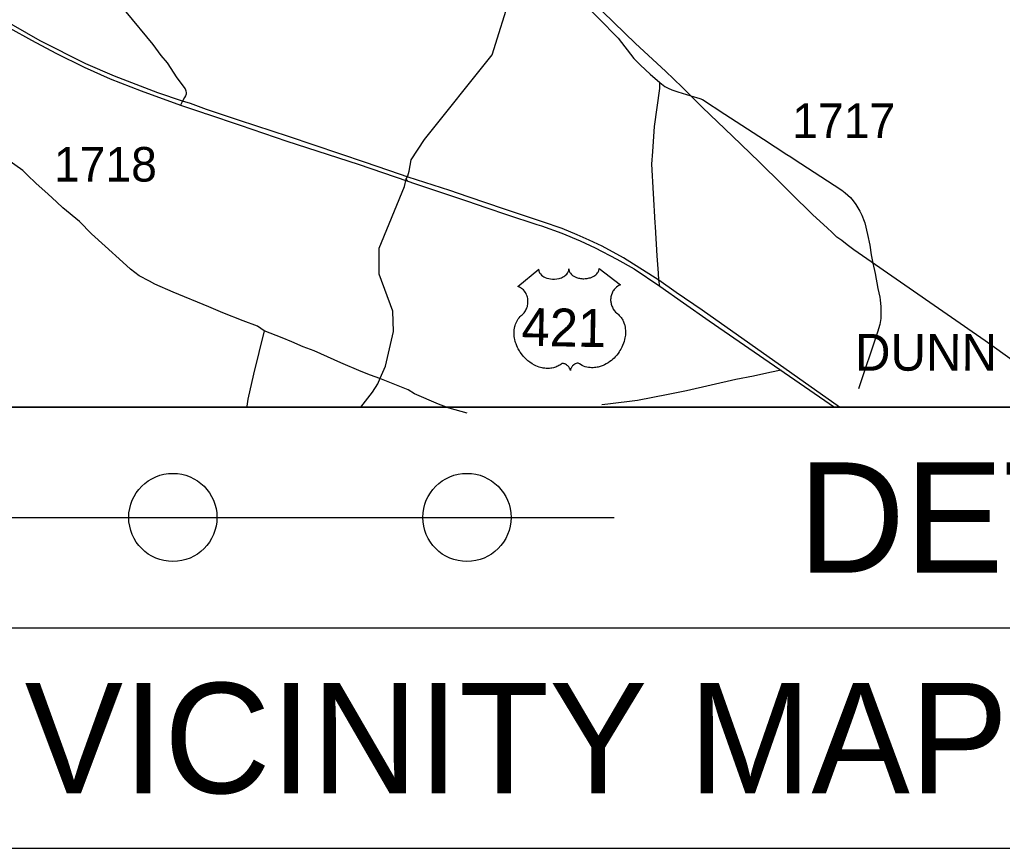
# Model space of a CAD drawing. Extents: x 0 to 2021, y 0 to 1321.
# Drawn here: x 408.2 to 541.9, y 888.1 to 1000.8 of the extents above; entities that cross this region are included whole.
import ezdxf

# ---------------------------------------------------------------- set-up
doc = ezdxf.new("R2010")
doc.units = 0
for name, color, linetype in [('Default', 7, 'Continuous'), ('Exist Hydro Stream or Body of Water', 7, 'Continuous'), ('Miscellaneous Lines', 7, 'Continuous'), ('Old_Level_26', 7, 'Continuous'), ('Scratch_Level_0', 7, 'Continuous'), ('Sheet Data Field CELL', 7, 'Continuous'), ('Sheet Title CELL', 7, 'Continuous'), ('Text', 7, 'Continuous')]:
    doc.layers.add(name, color=color, linetype=linetype)

msp = doc.modelspace()

# ---------------------------------------------------------------- linework, layer by layer
at = {"layer": 'Default'}
for p, q in [((475.98, 964.51), (478.81, 966.84)), ((478.82, 966.72), (478.81, 966.84)), ((478.82, 966.72), (478.85, 966.58)), ((482.83, 966.5), (482.89, 966.67)), ((482.89, 966.67), (482.91, 966.75)), ((482.91, 966.75), (482.92, 966.9)), ((482.92, 966.9), (482.93, 966.77)), ((482.93, 966.77), (482.94, 966.69)), ((482.94, 966.69), (482.97, 966.61)), ((482.97, 966.61), (483, 966.52)), ((486.93, 966.56), (486.98, 966.67)), ((486.98, 966.67), (487, 966.78)), ((487, 966.78), (487.02, 966.88)), ((487.02, 966.97), (489.92, 964.73)), ((487.02, 966.88), (487.02, 966.97)), ((478.85, 966.58), (478.88, 966.51)), ((478.88, 966.51), (478.94, 966.37)), ((478.94, 966.37), (479.06, 966.21)), ((479.06, 966.21), (479.21, 966.05)), ((479.21, 966.05), (479.38, 965.91)), ((479.38, 965.91), (479.5, 965.84)), ((479.5, 965.84), (479.7, 965.73)), ((479.7, 965.73), (479.92, 965.64)), ((479.92, 965.64), (480.17, 965.58)), ((480.17, 965.58), (480.42, 965.53)), ((480.42, 965.53), (480.7, 965.5)), ((480.7, 965.5), (480.97, 965.5)), ((480.97, 965.5), (481.26, 965.53)), ((481.26, 965.53), (481.59, 965.6)), ((481.59, 965.6), (481.74, 965.64)), ((481.74, 965.64), (481.9, 965.7)), ((481.9, 965.7), (482.06, 965.76)), ((482.06, 965.76), (482.23, 965.86)), ((482.23, 965.86), (482.36, 965.95)), ((482.36, 965.95), (482.47, 966.03)), ((482.47, 966.03), (482.62, 966.18)), ((482.62, 966.18), (482.74, 966.33)), ((482.74, 966.33), (482.79, 966.41)), ((482.79, 966.41), (482.83, 966.5)), ((483, 966.52), (483.06, 966.4)), ((483.06, 966.4), (483.13, 966.3)), ((483.13, 966.3), (483.26, 966.15)), ((483.26, 966.15), (483.34, 966.08)), ((483.34, 966.08), (483.42, 966.02)), ((483.42, 966.02), (483.61, 965.89)), ((483.61, 965.89), (483.84, 965.78)), ((483.84, 965.78), (483.96, 965.73)), ((483.96, 965.73), (484.07, 965.69)), ((484.07, 965.69), (484.22, 965.65)), ((484.22, 965.65), (484.37, 965.62)), ((484.37, 965.62), (484.52, 965.59)), ((484.52, 965.59), (484.67, 965.57)), ((484.67, 965.57), (484.83, 965.56)), ((484.83, 965.56), (484.95, 965.56)), ((484.95, 965.56), (485.11, 965.57)), ((485.11, 965.57), (485.25, 965.58)), ((485.25, 965.58), (485.4, 965.59)), ((485.4, 965.59), (485.56, 965.62)), ((485.56, 965.62), (485.69, 965.66)), ((485.69, 965.66), (485.86, 965.7)), ((485.86, 965.7), (486.02, 965.76)), ((486.02, 965.76), (486.15, 965.82)), ((486.15, 965.82), (486.33, 965.92)), ((486.33, 965.92), (486.47, 966.01)), ((486.47, 966.01), (486.58, 966.1)), ((486.58, 966.1), (486.7, 966.21)), ((486.7, 966.21), (486.82, 966.35)), ((486.82, 966.35), (486.89, 966.45)), ((486.89, 966.45), (486.93, 966.56)), ((476.07, 964.48), (475.98, 964.51)), ((476.21, 964.41), (476.07, 964.48)), ((476.36, 964.33), (476.21, 964.41)), ((476.48, 964.24), (476.36, 964.33)), ((476.6, 964.15), (476.48, 964.24)), ((476.73, 964.03), (476.6, 964.15)), ((476.86, 963.89), (476.73, 964.03)), ((488.99, 963.96), (488.91, 963.85)), ((489.07, 964.08), (488.99, 963.96)), ((489.13, 964.16), (489.07, 964.08)), ((489.21, 964.25), (489.13, 964.16)), ((489.29, 964.33), (489.21, 964.25)), ((489.38, 964.4), (489.29, 964.33)), ((489.57, 964.55), (489.38, 964.4)), ((489.7, 964.62), (489.57, 964.55)), ((489.85, 964.7), (489.7, 964.62)), ((489.92, 964.73), (489.85, 964.7)), ((476.98, 963.71), (476.86, 963.89)), ((477.09, 963.53), (476.98, 963.71)), ((477.16, 963.39), (477.09, 963.53)), ((477.23, 963.2), (477.16, 963.39)), ((477.28, 963.03), (477.23, 963.2)), ((477.32, 962.85), (477.28, 963.03)), ((477.35, 962.65), (477.32, 962.85)), ((477.35, 962.48), (477.35, 962.65)), ((488.61, 962.85), (488.6, 962.73)), ((488.6, 962.73), (488.6, 962.61)), ((488.6, 962.61), (488.61, 962.48)), ((488.64, 963.11), (488.61, 962.85)), ((488.67, 963.23), (488.64, 963.11)), ((488.71, 963.38), (488.67, 963.23)), ((488.79, 963.61), (488.71, 963.38)), ((488.84, 963.72), (488.79, 963.61)), ((488.91, 963.85), (488.84, 963.72)), ((477, 961.19), (477.07, 961.31)), ((477.07, 961.31), (477.15, 961.48)), ((477.15, 961.48), (477.2, 961.6)), ((477.2, 961.6), (477.27, 961.8)), ((477.27, 961.8), (477.3, 961.93)), ((477.3, 961.93), (477.33, 962.11)), ((477.33, 962.11), (477.35, 962.27)), ((477.35, 962.27), (477.35, 962.48)), ((488.61, 962.48), (488.63, 962.36)), ((488.63, 962.36), (488.65, 962.23)), ((488.65, 962.23), (488.67, 962.12)), ((488.67, 962.12), (488.71, 961.98)), ((488.71, 961.98), (488.76, 961.83)), ((488.76, 961.83), (488.83, 961.67)), ((488.83, 961.67), (488.96, 961.43)), ((488.96, 961.43), (489.14, 961.17)), ((475.83, 959.76), (475.92, 959.92)), ((475.92, 959.92), (476.03, 960.09)), ((476.03, 960.09), (476.14, 960.24)), ((476.14, 960.24), (476.28, 960.4)), ((476.28, 960.4), (476.43, 960.55)), ((476.43, 960.55), (476.57, 960.66)), ((476.57, 960.66), (476.74, 960.83)), ((476.74, 960.83), (476.82, 960.93)), ((476.82, 960.93), (476.92, 961.07)), ((476.92, 961.07), (477, 961.19)), ((489.14, 961.17), (489.26, 961.03)), ((489.26, 961.03), (489.38, 960.91)), ((489.38, 960.91), (489.56, 960.77)), ((489.56, 960.77), (489.65, 960.68)), ((489.65, 960.68), (489.77, 960.57)), ((489.77, 960.57), (489.95, 960.37)), ((489.95, 960.37), (490.02, 960.27)), ((490.02, 960.27), (490.1, 960.16)), ((490.1, 960.16), (490.17, 960.05)), ((490.17, 960.05), (490.24, 959.93)), ((490.24, 959.93), (490.29, 959.82)), ((475.47, 958.37), (475.49, 958.6)), ((475.49, 958.6), (475.52, 958.84)), ((475.52, 958.84), (475.56, 959.04)), ((475.56, 959.04), (475.6, 959.19)), ((475.6, 959.19), (475.66, 959.37)), ((475.66, 959.37), (475.74, 959.57)), ((475.74, 959.57), (475.83, 959.76)), ((490.29, 959.82), (490.4, 959.58)), ((490.4, 959.58), (490.47, 959.34)), ((490.47, 959.34), (490.51, 959.22)), ((490.51, 959.22), (490.57, 958.94)), ((490.57, 958.94), (490.59, 958.8)), ((490.59, 958.8), (490.62, 958.52)), ((475.46, 958.18), (475.47, 958.37)), ((475.47, 957.95), (475.46, 958.18)), ((475.49, 957.7), (475.47, 957.95)), ((475.53, 957.46), (475.49, 957.7)), ((475.56, 957.28), (475.53, 957.46)), ((475.62, 957.04), (475.56, 957.28)), ((490.5, 957.29), (490.43, 957.03)), ((490.55, 957.51), (490.5, 957.29)), ((490.6, 957.88), (490.55, 957.51)), ((490.62, 958.19), (490.6, 957.88)), ((490.62, 958.52), (490.62, 958.19)), ((475.66, 956.9), (475.62, 957.04)), ((475.74, 956.68), (475.66, 956.9)), ((475.82, 956.45), (475.74, 956.68)), ((475.94, 956.2), (475.82, 956.45)), ((476.02, 956.02), (475.94, 956.2)), ((476.18, 955.75), (476.02, 956.02)), ((489.97, 955.96), (489.87, 955.79)), ((490.12, 956.24), (489.97, 955.96)), ((490.23, 956.48), (490.12, 956.24)), ((490.36, 956.81), (490.23, 956.48)), ((490.43, 957.03), (490.36, 956.81)), ((476.29, 955.58), (476.18, 955.75)), ((476.45, 955.34), (476.29, 955.58)), ((476.71, 955.02), (476.45, 955.34)), ((476.87, 954.84), (476.71, 955.02)), ((477.15, 954.57), (476.87, 954.84)), ((477.33, 954.4), (477.15, 954.57)), ((488.84, 954.57), (488.7, 954.45)), ((489.06, 954.77), (488.84, 954.57)), ((489.23, 954.94), (489.06, 954.77)), ((489.44, 955.18), (489.23, 954.94)), ((489.61, 955.4), (489.44, 955.18)), ((489.76, 955.61), (489.61, 955.4)), ((489.87, 955.79), (489.76, 955.61)), ((477.59, 954.2), (477.33, 954.4)), ((477.93, 953.97), (477.59, 954.2)), ((478.22, 953.81), (477.93, 953.97)), ((478.4, 953.72), (478.22, 953.81)), ((478.66, 953.61), (478.4, 953.72)), ((478.87, 953.54), (478.66, 953.61)), ((479.07, 953.48), (478.87, 953.54)), ((479.26, 953.43), (479.07, 953.48)), ((479.44, 953.39), (479.26, 953.43)), ((479.65, 953.37), (479.44, 953.39)), ((479.83, 953.35), (479.65, 953.37)), ((479.98, 953.34), (479.83, 953.35)), ((480.14, 953.34), (479.98, 953.34)), ((480.29, 953.35), (480.14, 953.34)), ((480.47, 953.37), (480.29, 953.35)), ((480.62, 953.4), (480.47, 953.37)), ((480.81, 953.43), (480.62, 953.4)), ((480.98, 953.48), (480.81, 953.43)), ((481.14, 953.54), (480.98, 953.48)), ((481.28, 953.6), (481.14, 953.54)), ((481.4, 953.65), (481.28, 953.6)), ((481.55, 953.74), (481.4, 953.65)), ((481.69, 953.82), (481.55, 953.74)), ((481.81, 953.91), (481.69, 953.82)), ((481.94, 954.01), (481.81, 953.91)), ((482.03, 954.03), (481.94, 954.01)), ((482.1, 954.03), (482.03, 954.03)), ((482.19, 954.03), (482.1, 954.03)), ((482.29, 954), (482.19, 954.03)), ((482.37, 953.97), (482.29, 954)), ((482.47, 953.92), (482.37, 953.97)), ((482.58, 953.86), (482.47, 953.92)), ((482.69, 953.77), (482.58, 953.86)), ((482.78, 953.69), (482.69, 953.77)), ((482.89, 953.57), (482.78, 953.69)), ((482.95, 953.48), (482.89, 953.57)), ((483.01, 953.38), (482.95, 953.48)), ((483.07, 953.26), (483.01, 953.38)), ((483.12, 953.09), (483.07, 953.26)), ((483.15, 953.23), (483.12, 953.09)), ((483.18, 953.33), (483.15, 953.23)), ((483.22, 953.4), (483.18, 953.33)), ((483.31, 953.56), (483.22, 953.4)), ((483.36, 953.62), (483.31, 953.56)), ((483.43, 953.7), (483.36, 953.62)), ((483.53, 953.79), (483.43, 953.7)), ((483.61, 953.86), (483.53, 953.79)), ((483.71, 953.93), (483.61, 953.86)), ((483.79, 953.97), (483.71, 953.93)), ((483.92, 954.03), (483.79, 953.97)), ((484.05, 954.06), (483.92, 954.03)), ((484.19, 954.05), (484.05, 954.06)), ((484.25, 954.04), (484.19, 954.05)), ((484.35, 953.99), (484.25, 954.04)), ((484.71, 953.77), (484.35, 953.99)), ((484.92, 953.67), (484.71, 953.77)), ((485.13, 953.59), (484.92, 953.67)), ((485.36, 953.53), (485.13, 953.59)), ((485.58, 953.48), (485.36, 953.53)), ((485.79, 953.46), (485.58, 953.48)), ((486.01, 953.44), (485.79, 953.46)), ((486.23, 953.44), (486.01, 953.44)), ((486.4, 953.46), (486.23, 953.44)), ((486.57, 953.48), (486.4, 953.46)), ((486.75, 953.51), (486.57, 953.48)), ((486.9, 953.54), (486.75, 953.51)), ((487.33, 953.66), (486.9, 953.54)), ((487.58, 953.76), (487.33, 953.66)), ((487.77, 953.85), (487.58, 953.76)), ((487.99, 953.97), (487.77, 953.85)), ((488.25, 954.12), (487.99, 953.97)), ((488.51, 954.3), (488.25, 954.12)), ((488.7, 954.45), (488.51, 954.3))]:
    msp.add_line(p, q, dxfattribs=at)
for points in [[(405.18, 1000.57), (406.85, 999.66), (409.81, 998.01), (413.1, 996.25), (416.96, 994.35), (420.49, 992.77), (424.73, 991.12), (430.09, 989.18)], [(430.33, 989.73), (427.01, 990.86), (421.08, 993.12), (417.19, 994.81), (411, 997.95), (405.51, 1001.06)], [(430.33, 989.73), (430.09, 989.18)], [(461.03, 979.38), (459.86, 979.78), (455.27, 981.39), (444.76, 984.91), (438.09, 987.07), (433.62, 988.58), (431.45, 989.39), (430.33, 989.73)], [(430.09, 989.18), (433.08, 988.19), (433.45, 988.06), (433.62, 988), (438.18, 986.46), (444.55, 984.29), (454.23, 981.15), (460.99, 978.82), (460.8, 979.09), (460.71, 979.11)], [(460.99, 978.82), (461.9, 978.54), (469.01, 976.16), (471.76, 975.22), (474.42, 974.32), (478.56, 972.94), (479.2, 972.76), (481.96, 971.76), (484.47, 970.71), (486.49, 969.76), (489.46, 968.24), (491.78, 966.9), (495.27, 964.54)], [(495.17, 965.38), (490.35, 968.41), (487.46, 969.97), (485.67, 970.83), (484.05, 971.54), (482.02, 972.39), (479.32, 973.3), (474.14, 975.03), (469.2, 976.7), (466.7, 977.55), (461.03, 979.38)], [(495.27, 964.54), (495.17, 965.38)], [(519.72, 948.09), (501.03, 961.29), (497.5, 963.69), (495.17, 965.38)], [(495.27, 964.54), (498.53, 962.29), (502.02, 959.85), (519.04, 948.09)], [(469.08, 947.27), (466.61, 947.94), (465.18, 948.5), (461.92, 949.91), (461.06, 950.43), (457.19, 951.97)]]:
    msp.add_lwpolyline(points, dxfattribs=at)
at = {"layer": 'Exist Hydro Stream or Body of Water'}
for points in [[(460.8, 979.09), (460.89, 979.34), (460.99, 979.58), (461.17, 980.18), (461.44, 981.72), (463.29, 984.51), (472.46, 996.02), (475.06, 1004.31)], [(454.62, 948.09), (456.19, 950.11), (456.94, 951.27), (457.26, 952.05), (457.96, 953.68), (459.06, 958.4), (458.96, 961.13), (457.1, 966.19), (457.09, 969.71), (460.57, 978.12), (460.8, 979.09)]]:
    msp.add_lwpolyline(points, dxfattribs=at)
at = {"layer": 'Miscellaneous Lines'}
msp.add_line((369.03, 933.08), (489.06, 933.08), dxfattribs=at)
msp.add_lwpolyline([(552.18, 948.09), (539.54, 957.1), (522.84, 968.69), (521.68, 969.5), (520.76, 970.19), (520.04, 970.75), (519.36, 971.21), (518.69, 971.88), (518.09, 972.44), (517.06, 973.39), (516.12, 974.26), (513.12, 977.21), (511.97, 978.35), (508.82, 981.45), (505.19, 984.95), (501.1, 988.85), (499, 990.94), (498.33, 991.61), (496.07, 993.8), (491.97, 997.58), (484.56, 1004.84)], dxfattribs=at)
for centre in [(429.04, 933.08), (469.05, 933.08)]:
    msp.add_ellipse(centre, major_axis=(0, 6), ratio=0.999692, dxfattribs=at)
at = {"layer": 'Old_Level_26'}
for points in [[(419.1, 1010.98), (419.23, 1009.72), (419.27, 1009.27), (419.25, 1008.78), (419.41, 1006.81), (419.58, 1006.1), (419.84, 1005.66), (422.66, 1001.88), (426.33, 997.45), (427.4, 995.93), (428.25, 994.94), (429.58, 992.88), (430.7, 991.4), (430.82, 991.14), (430.85, 990.87), (430.85, 990.69), (430.76, 990.43), (430.64, 990.21), (430.33, 989.73)], [(478.23, 1009.37), (482.69, 1005.31), (484.29, 1003.77), (489.63, 998.27), (491.74, 995.51), (492.66, 994.6), (493.99, 993.38), (495.3, 992.28)], [(495.17, 965.38), (495.11, 966.3), (494.92, 968.68), (494.72, 972.63), (494.65, 973.16), (494.2, 981.15), (494.34, 982.85), (494.57, 986.28), (495.29, 991.43), (495.3, 992.28)], [(495.3, 992.28), (495.96, 991.72), (496.44, 991.47), (496.94, 991.25), (497.73, 990.97), (499.49, 990.45)], [(499.49, 990.45), (500.71, 990.08), (501.11, 989.93), (504.15, 987.96), (508.75, 984.95), (509.41, 984.53), (512.59, 982.47), (513.09, 982.15), (513.58, 981.82), (519, 978.31), (520.04, 977.62), (520.52, 977.27), (521.24, 976.63), (521.57, 976.15), (521.95, 975.64), (522.48, 974.74), (522.75, 974.22), (523.11, 973.39), (523.19, 973.18), (523.55, 971.59), (523.84, 970.11), (524.05, 968.79), (524.28, 967.69)], [(441.47, 958.47), (440.54, 959.09), (438.6, 959.81), (435.86, 960.9), (433.92, 961.73), (429.1, 963.75), (426.61, 964.84), (425.87, 965.21), (424.47, 965.96), (423.28, 966.85), (422.22, 967.8), (419.84, 969.97), (417.99, 971.65), (416.32, 973.33), (414.09, 975.2), (413.25, 975.99), (412.01, 977.1), (411.25, 977.8), (410.41, 978.55), (409.26, 979.67), (408.65, 980.3), (406.44, 981.84), (403.99, 983.62), (399.1, 986.58)], [(524.28, 967.69), (524.57, 966.26), (524.93, 964.23), (525.21, 963.03), (525.27, 962.68), (525.35, 961.75), (525.37, 960.63), (525.34, 960.15), (525.2, 959.32), (524.89, 958.29), (522.32, 950.58)], [(441.47, 958.47), (440.03, 952.56), (439.23, 949.16), (439.09, 948.23), (439.11, 948.09)], [(457.19, 951.97), (455.94, 952.42), (454.64, 952.95), (451.9, 954.11), (448.28, 955.75), (446.78, 956.3), (445.22, 956.96), (443.91, 957.53), (441.47, 958.47)], [(511.79, 953.11), (510.24, 952.8), (508.05, 952.31), (505.64, 951.83), (498.9, 950.32), (496.43, 949.8), (492.23, 948.98), (488.2, 948.49), (487.39, 948.41)]]:
    msp.add_lwpolyline(points, dxfattribs=at)
at = {"layer": 'Scratch_Level_0'}
msp.add_lwpolyline([(318.71, 1236.23), (654.77, 1236.23), (654.77, 948.09), (318.71, 948.09)], close=True, dxfattribs=at)
at = {"layer": 'Sheet Title CELL'}
for p, q in [((318.71, 948.09), (654.77, 948.09)), ((318.71, 918.07), (654.77, 918.07)), ((318.71, 888.06), (654.77, 888.06))]:
    msp.add_line(p, q, dxfattribs=at)

# ---------------------------------------------------------------- texts
at = {"layer": 'Default'}
msp.add_text('421', height=5.153, rotation=358.9625, dxfattribs=at).set_placement((476.44, 956.45))
at = {"layer": 'Sheet Data Field CELL'}
msp.add_text('DETOUR', height=15.007, rotation=360, dxfattribs=at).set_placement((514.14, 925.57))
msp.add_text('VICINITY MAP', height=15.0075, dxfattribs=at).set_placement((408.88, 895.56))
at = {"layer": 'Text'}
for s, height, rotation, p in [('1717', 4.705, 360, (513.31, 984.7)), ('1718', 4.705, 360, (412.87, 978.78)), ('DUNN', 5, 359.915, (521.84, 953.06))]:
    msp.add_text(s, height=height, rotation=rotation, dxfattribs=at).set_placement(p)

doc.saveas('drawing.dxf')
